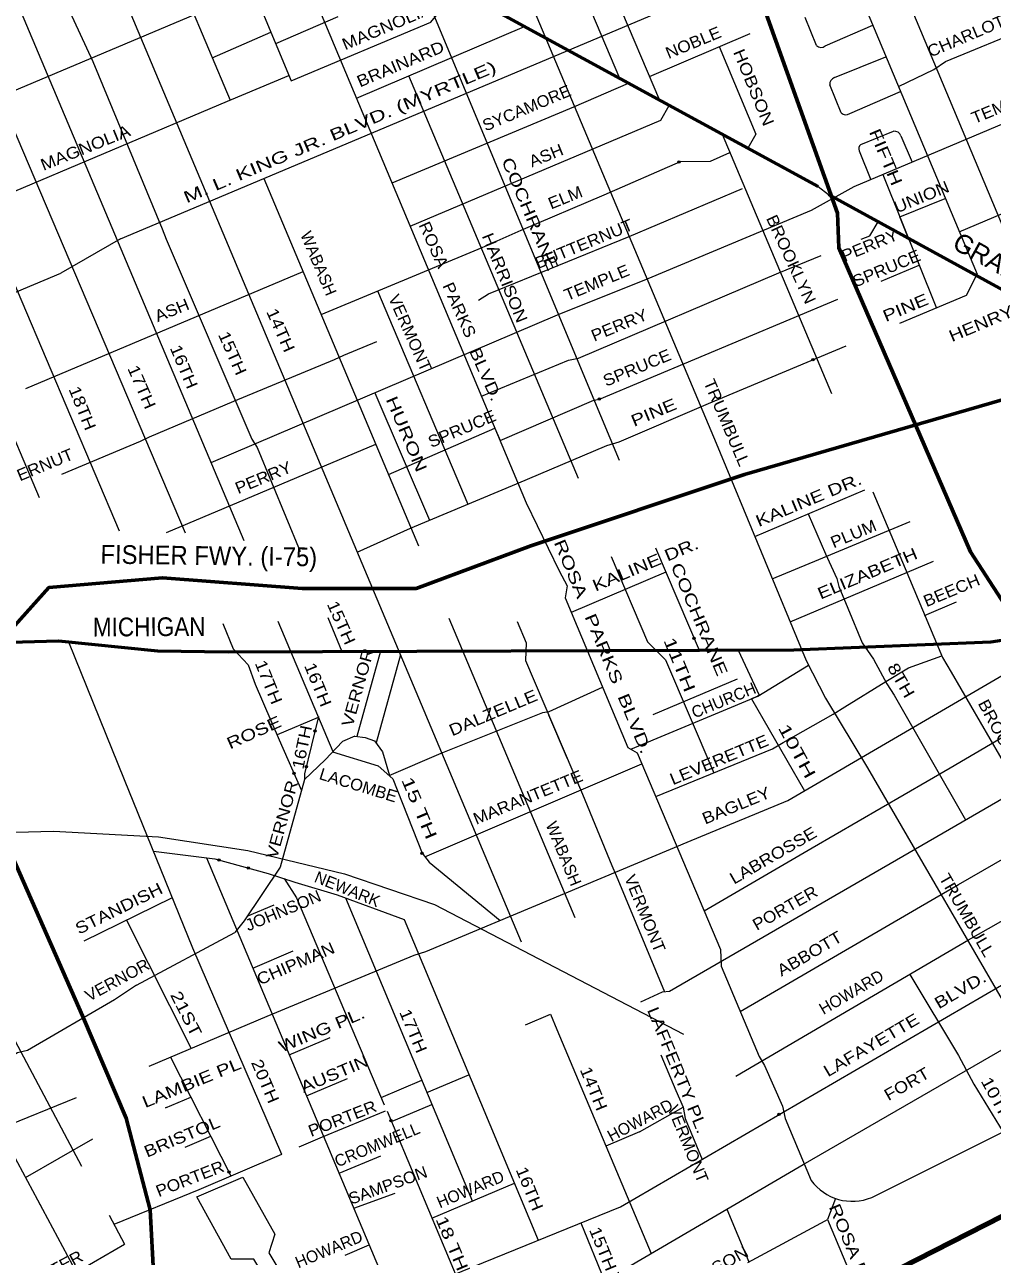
# Model space of a CAD drawing. Extents: x 34705 to 138605, y 34275 to 143551.
# Drawn here: x 89542 to 95747, y 96052 to 103945 of the extents above; entities that cross this region are included whole.
import ezdxf
from ezdxf.enums import TextEntityAlignment as Align

# ---------------------------------------------------------------- set-up
doc = ezdxf.new("R2010")
doc.units = 0
doc.header["$LTSCALE"] = 30
doc.header["$PDMODE"] = 32
doc.header["$PDSIZE"] = 15
doc.linetypes.add('MEDIUM_DASHED', pattern=[4.5, 3, -1.5])
for name, color, linetype, lineweight in [('1', 7, 'Continuous', 13), ('11', 7, 'Continuous', 13), ('50', 7, 'Continuous', 13), ('51', 7, 'Continuous', 35), ('58', 7, 'Continuous', 106), ('7', 7, 'MEDIUM_DASHED', 25)]:
    doc.layers.add(name, color=color, linetype=linetype, lineweight=lineweight)

msp = doc.modelspace()

# ---------------------------------------------------------------- linework, layer by layer
at = {"layer": '1'}
for p, q in [((88037.22, 107540.27), (90948.84, 100639.76)), ((92437.6, 106228.47), (93613.46, 103461.04)), ((94745.68, 104500.34), (95648.75, 102345.66)), ((91152.1, 103823.55), (91552.57, 103996.12)), ((94619.68, 103812.39), (94546.47, 103991.39)), ((90745.12, 103733), (91121.82, 103896.3)), ((91669.67, 103473.66), (92746.84, 103933.49)), ((93548.7, 103613.46), (94194.7, 103888.8)), ((94675.05, 103808.6), (94980.28, 103940.6)), ((93996.19, 103804.19), (94230.25, 103242.58)), ((94734.54, 103606), (95064.71, 103739.14)), ((90843.31, 103454.28), (91236.85, 103620)), ((94776.95, 103380.26), (94703.75, 103559.27)), ((89381.11, 103482.68), (90572.51, 100689.56)), ((94832.32, 103376.48), (95157.73, 103517.2)), ((88062.65, 102279.34), (90843.31, 103454.28)), ((89037.16, 103313.44), (90149.28, 100700.72)), ((94013.89, 103242.74), (94714.56, 101581.4)), ((94230.25, 103242.58), (94179.53, 103152.43)), ((94903.15, 103177.3), (95113.06, 103262.47)), ((95534.49, 102618.28), (96994.31, 103237.44)), ((95159.9, 103231.84), (95231.73, 103063.63)), ((94892.09, 103135.38), (94966.65, 102951.54)), ((91075.9, 102959.3), (92067.49, 100605.59)), ((95045.43, 102984.85), (95387.56, 102129.26)), ((94629.96, 102906.87), (94695.3, 102855.98)), ((90156.4, 102571.65), (89773.72, 102353.27)), ((95034.72, 102302.23), (95277.73, 102403.92)), ((89549.39, 101612.85), (91327.22, 102362.74)), ((91805, 102238.82), (92383.71, 100872.42)), ((89098.43, 102178.67), (89636.65, 100915.24)), ((91587.9, 101826.14), (91801.28, 101914.56)), ((91528.44, 101798.88), (91587.9, 101826.14)), ((90884.05, 101533.29), (91528.44, 101798.88)), ((91787.73, 101586.31), (92138.37, 100769.63)), ((89780.64, 101064.95), (90284.72, 101276.65)), ((90452.82, 100690.52), (91793.11, 101256.87)), ((91032.38, 101234.69), (91309.88, 100569.02)), ((94223.03, 100665.67), (94929.82, 100964.58)), ((93587.54, 100592.75), (93866.9, 99936.69)), ((94449.46, 100119.12), (95368.3, 100507.63)), ((93654.05, 100436.56), (93047, 100178.27)), ((95311.37, 100159.92), (95517.21, 100246.55)), ((91166.67, 100123.5), (91519.18, 99288.06)), ((91486.37, 100145.62), (91576.53, 99929.33)), ((92262.51, 100142.67), (93070.7, 98224.26)), ((93454.96, 96423.05), (99604.05, 99999.77)), ((91823.24, 99930.13), (91671.36, 99384.63)), ((91951.93, 99906.72), (91795.22, 99343.87)), ((94110.78, 99751.32), (93569.1, 99522.69)), ((91424.36, 99506.23), (91161.15, 99394.09)), ((91425.57, 99511.28), (91337.49, 99143.57)), ((92901.21, 99521.86), (93020.57, 99243.3)), ((91337.49, 99143.57), (91336.78, 99108.32)), ((92107.56, 98612.52), (93500.09, 99207.94)), ((90708, 98606.4), (92126.39, 95234.65)), ((93307.86, 98556.65), (93334.46, 98492.7)), ((93334.46, 98492.7), (93644.9, 97748.07)), ((89923.25, 98074.43), (90486.88, 98349.11)), ((91599.26, 98350.22), (92413.75, 96404.47)), ((88600.2, 98320.64), (90094.32, 95540.39)), ((90969.3, 98231.87), (91142.91, 98304.73)), ((90195.89, 98207.29), (90610.04, 97385.31)), ((91975.11, 98211.71), (92834.39, 96155.62)), ((90259.92, 97790.34), (90889.94, 98128.12)), ((89174.85, 98007.64), (89907.59, 96630.12)), ((91005.9, 97898.23), (91265.01, 98010.97)), ((92754, 97536.28), (92913.24, 97605.16)), ((91238.88, 97344.39), (91501.02, 97454.29)), ((90478.01, 97329.29), (90865.3, 96567.9)), ((94251.36, 97332.72), (94286.71, 97275.58)), ((94286.71, 97275.58), (94402.21, 97015.42)), ((91349.31, 97081.89), (91611.58, 97191.93)), ((91828.26, 97070.64), (92088.92, 97180.46)), ((92121.72, 97102.11), (92391.36, 97215.71)), ((91893.74, 96916.4), (92153.62, 97025.89)), ((93484.94, 96850.76), (93764.35, 97008.33)), ((94402.21, 97015.42), (94418.35, 96935.67)), ((91452.89, 96818.14), (91857.09, 96986.06)), ((91866.2, 96982.02), (92506.68, 95456.18)), ((94418.35, 96935.67), (94584.93, 96539.62)), ((93484.94, 96850.76), (93269.31, 96757.91)), ((89547.78, 96557.39), (89980.72, 96806.42)), ((90571.64, 96752.54), (90736.19, 96821.72)), ((91302.98, 96754.82), (91452.89, 96818.14)), ((91558.13, 96585.5), (91825.32, 96695.89)), ((91652.75, 96360.58), (91918.43, 96457.22)), ((92154.07, 96296.22), (92682.47, 96520.62)), ((93363.13, 96369.94), (93454.96, 96423.05)), ((94741.71, 96423.35), (94690.14, 96289.45)), ((90084.45, 96317.4), (90183.38, 96131.41)), ((94044.06, 96354.84), (94185.15, 96016.57)), ((94690.14, 96289.45), (94886.57, 95822.43)), ((93108.35, 96266.62), (93259.29, 95894.99)), ((91597.05, 96059.99), (91751.36, 96126.15))]:
    msp.add_line(p, q, dxfattribs=at)
at = {"layer": '1', "lineweight": 53}
for p, q in [((90110.84, 105370.56), (94629.96, 102906.87)), ((94695.3, 102855.98), (98364.86, 100847.24))]:
    msp.add_line(p, q, dxfattribs=at)
at = {"layer": '1'}
for points in [[(81747.75, 122290.24), (81921.27, 121957.09), (82052.47, 121930.85), (82118.06, 121884.91), (82590.36, 120959.69), (82629.72, 120926.88), (83141.38, 119927.85), (83541.52, 119133.87), (83541.52, 119022.31), (83495.61, 118937.01), (83436.57, 118877.95), (83449.69, 118733.59), (83456.25, 118661.41), (87277.28, 110821.66), (87605.27, 110172.03), (87736.46, 109929.24), (90285.3, 103864.22), (92725.99, 98068.68)], [(87924.47, 112104.52), (87935.44, 111856.64), (88221.88, 111308.88), (88769.61, 110355.76), (90167.23, 107043.23), (90212.11, 106947.03), (92757.3, 100881.83), (92968.86, 100445.74), (93020.15, 100349.54), (93007.33, 100272.59), (93410.61, 99313.84), (93470.43, 99278.08), (94003.29, 98018.06), (94007.57, 97912.37), (94251.36, 97332.72)], [(89620.31, 111530.82), (91301.99, 107601.17), (91366.1, 107415.19), (91673.83, 106703.33), (92808.58, 104033.88), (93975.39, 101263.41), (94552.01, 99871.59), (94676.64, 99628.81), (94945.59, 99182.6), (95948.05, 97457.03)], [(93695.7, 107547.6), (93857.2, 107315.71), (95985.91, 102236.51)], [(92273.44, 106158.02), (92495.54, 105632.89), (93356.65, 103601.04)], [(89318.01, 106151.54), (89120.57, 106072.53), (89061.53, 105947.86), (89061.53, 105862.55), (89709.3, 104295.91), (89979.33, 103708.16), (90424.31, 102635.76), (90450.55, 102570.15)], [(90045.33, 105405.98), (90304.59, 104779.85), (90859.58, 103460.99)], [(90576.58, 105116.66), (90647.47, 105035.61), (91251.37, 103585.13)], [(95144.29, 103549.28), (95370.73, 103656.57), (95446.38, 103708.96), (95987.58, 103930.16), (96605.73, 104193.38), (96625.21, 104146.06), (96936.12, 104314.36), (97524.26, 104662.79)], [(90156.4, 102571.65), (94024.26, 104202.29), (94870.72, 104551.4)], [(90738.5, 101138.28), (92958.63, 102086.3), (93540.56, 102319.15), (94588.03, 102755.74), (94861.54, 102907.09), (96744.08, 103703.14), (96837.19, 103772.99), (97713.93, 104285.09)], [(87827, 102821.34), (88640.53, 103170.17), (91008.18, 104169.25)], [(92137.1, 104071.39), (93174.01, 101584.06), (93353.56, 101153.61)], [(91251.37, 103585.13), (92146.6, 103961.27), (92198.44, 104022.64)], [(91899.52, 102930.38), (93063.38, 103419.35), (93413.35, 103570.13)], [(92003.56, 103618.4), (92764.49, 101813.89), (93091.94, 101038.9)], [(92013.86, 102653.46), (93622.03, 103332.04), (93674.28, 103427.88)], [(93747.05, 103068.19), (93938.65, 103070.68), (94063.57, 103124.95)], [(91442.75, 102088.53), (92475.63, 102517.07), (92725.86, 102627.67), (93258.25, 102855.05), (93747.05, 103068.19)], [(92452.35, 102179.44), (92452.35, 102179.44), (92516.36, 102220.19), (93418.35, 102586.93), (94145.77, 102895.45)], [(94905.78, 102569.96), (94960.47, 102592.75), (95015.25, 102680.83), (95209.52, 102574.49), (95153.93, 102713.52), (95445.05, 102831.67)], [(90450.55, 102570.15), (90999.7, 101288.86), (91032.38, 101234.69)], [(92471.07, 101563.91), (93028.46, 101795.25), (93092.47, 101806.89), (94378.54, 102354.08), (94649.7, 102465.05)], [(87161.55, 101274.03), (87939.48, 101579.86), (88306.1, 101737.03), (89773.72, 102353.27)], [(95154.26, 102031.87), (95581.68, 102211.46), (95648.75, 102345.66)], [(91874.75, 101063.07), (92557.1, 101358.91), (92590.23, 101279.95), (93192.43, 101539.65), (93227.43, 101545.94), (94755.83, 102185.52)], [(91674.88, 100564.59), (92015.9, 100718.33), (92696.76, 101003.57), (93274.99, 101247.95), (93354.76, 101270.88), (93927.53, 101516.4), (94810.38, 101887.37)], [(90284.72, 101276.65), (90342.86, 101304.06), (90884.05, 101533.29)], [(94980.43, 100951.02), (95187.4, 100460.27), (95427.18, 99889.61), (95483.49, 99796.13), (95916.43, 99048.07)], [(94565.73, 100810.6), (94676.64, 100554.03), (94748.8, 100396.54), (94761.92, 100344.05), (94820.96, 100206.25), (94912.79, 99983.15), (94984.95, 99878.16), (95070.22, 99720.67), (95116.14, 99648.49), (95573.72, 98849.07)], [(94335.77, 100393.54), (94634.18, 100517.44), (95220.13, 100760.84)], [(93303.85, 100537.36), (93535.25, 99989.71), (93650.47, 99873.89), (93961.12, 99151.55)], [(90812.65, 100107.58), (90879.88, 99944.8), (90975.33, 99843.7), (91021.24, 99719.03), (91174.64, 99362.74), (91317.4, 99038.36)], [(92700.97, 100119.46), (92757.93, 99984.79), (92753.93, 99869.87)], [(89822.75, 99990.51), (90181.6, 99108.77), (90619.46, 98029.36), (91188.7, 96706.54)], [(94116.67, 99937.49), (94252.63, 99648.61), (94243.24, 99642.87), (94202.04, 99625.67), (94542.7, 99036.08)], [(92753.93, 99869.87), (93118.14, 99014), (93307.86, 98556.65)], [(93428.89, 99302.91), (94243.24, 99642.87), (94567.63, 99841.17)], [(93588.48, 98998.92), (94336.35, 99305.24), (94406.18, 99345.99), (94726.24, 99526.44), (94801.89, 99573.01), (95063.76, 99736), (95209.24, 99823.32), (95422.36, 99900.85)], [(90341.13, 97271.2), (91097.91, 97592.35), (92040.63, 97982.37), (92114.36, 98006.08), (93683.61, 98661.67), (93789.34, 98705.66), (94435.28, 98973.43), (95918.22, 99838.32)], [(68439.64, 83130.91), (69240.62, 83379.94), (69351.18, 83443.98), (71166.8, 83996.99), (73724.39, 85148.13), (74227.76, 85392.62), (75135.57, 85904.88), (77195.6, 86958.51), (78743.53, 87721.08), (81322.94, 89059.96), (82067.81, 89449.98), (83313.14, 90160.16), (86113.68, 91749.34), (89963.15, 93974.49), (93143.39, 95827.08), (94534.21, 96642.05), (99929.58, 99752.11)], [(91880.28, 99133.8), (92212.31, 99276.13), (92864.07, 99538.08), (92904.8, 99543.91), (93248.17, 99700.03)], [(93898.5, 98265.83), (94592.4, 98670.73), (95476.93, 99182.99), (96092.18, 99543.48)], [(94102.64, 97206.72), (95593.32, 98079.88), (96600.06, 98650.35), (98206.88, 99594.86)], [(91660.2, 99386.35), (91579.35, 99350.97), (91468.17, 99234.7), (91336.78, 99108.32), (91181.39, 98547.2), (90950.19, 98203.45), (90889.94, 98128.12)], [(91660.2, 99386.35), (91725.9, 99376.24), (91786.54, 99356.02), (91837.08, 99285.25), (91881.56, 99132.68)], [(91516.89, 99285.66), (91808.8, 99196.37), (91903.88, 99113.14), (92090.1, 98635.8)], [(93492.55, 97684.04), (93632.22, 97748.07), (93677.3, 97751.12), (95511.85, 98813.35), (96265.19, 99248.27)], [(94130.13, 97620.96), (95378, 98347.65), (95529.31, 98434.97), (96436.14, 98956.57)], [(90368.05, 98649.12), (90761.13, 98599.72), (91103.14, 98505.9)], [(92090.1, 98635.8), (92136.66, 98577.59), (92591.86, 98205.57)], [(91103.14, 98505.9), (91274.65, 98451.22), (91546.85, 98369.54), (91975.11, 98211.71)], [(91207.21, 98472.72), (91286.45, 98350.34), (91848.51, 97022.81)], [(90259.92, 97790.34), (90118.26, 97696.67), (89560.52, 97372.09), (89497, 97356.72), (89242.4, 97205.72), (89176.52, 97200.37)], [(95216.66, 97857.76), (95529.41, 97338.72), (95627.8, 97154.99), (95815.09, 96848.98)], [(92913.24, 97605.16), (92954.72, 97506.05), (93558.44, 96070.29)], [(93620.98, 97343.08), (93717.83, 97114.7), (93764.01, 97009.1), (93777.15, 96936.87), (93886.16, 96673.86)], [(94973.04, 96430.02), (95820.27, 96851.61), (96531.68, 97212.52), (96828.47, 97381.34)], [(87348.77, 95890.22), (87903.33, 96185.57), (87941.55, 96113.13), (88633.43, 96486.33), (88988.41, 96672.61), (89378.3, 96870.53), (89874.49, 97069.92)], [(90451.05, 97006.43), (90446.15, 97004.41), (90608.34, 97073.06)], [(90116.07, 96257.96), (90661.46, 96480.51), (91191.02, 96707.53)], [(91747.97, 95706.14), (91889.33, 95767.41), (92279.23, 95930.4), (93363.13, 96369.94)], [(94179.23, 96013.36), (94673.87, 96281.14), (94690.23, 96289.28)], [(88815.04, 95358.99), (89488.25, 95726.62), (89850.55, 95937.47), (90183.38, 96131.41)]]:
    msp.add_lwpolyline(points, dxfattribs=at)
at = {"layer": '1', "lineweight": 53}
msp.add_lwpolyline([(70273.25, 98655.39), (71057.35, 98936.8), (71901.7, 99280.47), (72734.73, 99461.12), (73549.47, 99618.3), (74194.43, 99751.98), (74462.66, 99868.63), (74760.14, 99892.09), (75412.24, 99851.32), (76511.78, 99857.14), (78835.21, 99868.78), (80080.52, 99857.14), (86770.24, 99915.34), (86956.45, 99956.09), (88909.68, 99973.56), (89759.8, 99996.86), (90394.28, 99932.82), (90847.72, 99926.99), (94474.35, 99938.64), (95736.38, 99991), (96334.87, 100081.57)], dxfattribs=at)
at = {"layer": '1'}
for centre, radius, start, end in [((94649.33, 103839.35), 40.08, 222.27388, 309.90416), ((94749.23, 103562.8), 45.63, 108.79235, 184.44263), ((94806.61, 103407.23), 40.08, 222.27388, 309.90416), ((95116.76, 103216.99), 45.63, 18.99808, 94.64837), ((94930.22, 103147.74), 40.08, 132.47962, 197.95901), ((94848.59, 96731.32), 325.99, 216.0192, 292.44115)]:
    msp.add_arc(centre, radius, start, end, dxfattribs=at)
for p in [(93738.42, 103064.26), (94404.36, 103029.86), (94595.87, 101797.56), (93227.43, 101545.94), (93834.52, 100012.74), (91403.67, 99419.83), (91269.4, 99147.43), (91348.63, 99190.09), (90789.33, 98591.98), (92090.1, 98635.8), (90975.79, 98540.83), (91891.37, 96922.04), (94379.58, 96962.18), (90852.84, 96592.4)]:
    msp.add_point(p, dxfattribs=at)
at = {"layer": '50'}
msp.add_line((92169.12, 98306.86), (93766.07, 97476.34), dxfattribs=at)
msp.add_lwpolyline([(72952.8, 95508.64), (78064.89, 96622.26), (81430.09, 97291.04), (86167.76, 98196.23), (89160.46, 98763.08), (89727.54, 98776.38), (90401.7, 98740.87), (90973.35, 98653.39), (91592.71, 98503.02), (92169.12, 98306.86)], dxfattribs=at)
at = {"layer": '51', "lineweight": 60}
for points in [[(89237.66, 115479.85), (91499.64, 110952.67), (93420.76, 106565.37), (94042.42, 104827.01), (94275.43, 104074.61), (94754.53, 102737.63), (94761.52, 102513.8), (95607.58, 100567.59), (95901.26, 100112.95), (96166.96, 99847.16), (96705.36, 99210.66), (97075.95, 98895.9), (97236.78, 98686.07), (97390.6, 98581.15), (97562.53, 98387.67)], [(100708.3, 104431.99), (100301.7, 104046.37), (99460.75, 103701.33), (98388.89, 103068.27), (97510.88, 102543.58), (96878.03, 102018.88), (96266.56, 101672.41), (94157.06, 101062.17), (92788.73, 100605.91), (92053.25, 100332.16), (91322.06, 100332.16), (90426.94, 100400.6), (89697.17, 100337.86), (89332.28, 99932.93), (89286.67, 99488.08), (89309.48, 99071.74), (89383.59, 98792.29), (89913.82, 97593.19), (90193.19, 96937.32), (90347.13, 96349.89), (90369.93, 95910.74)]]:
    msp.add_lwpolyline(points, dxfattribs=at)
at = {"layer": '58'}
msp.add_lwpolyline([(109288.57, 102020.28), (107945.92, 101285.08), (107188.24, 100823.21), (106858.2, 100701.93), (106111.49, 100351.64), (105606.31, 100041.45), (105294.49, 99854.44), (104132.31, 99432.6), (103251.52, 99077.41), (102563.33, 98804.04), (102396.46, 98745.29), (102193.7, 98668.47), (101874.28, 98521.51), (101323.51, 98272.16), (101245.34, 98201.3), (98594.35, 97249.65), (98526.88, 97383.5), (96460.77, 96641.8), (94939.86, 95864.74)], dxfattribs=at)
at = {"layer": '7', "linetype": 'Continuous', "lineweight": 13}
msp.add_lwpolyline([(90940.86, 96561), (91145.86, 96195.59), (91107.24, 96075.3), (93932.18, 91369.35), (93844.25, 91320.13), (91012.91, 96033.52), (90866.14, 96033.62), (90647.37, 96433.23)], close=True, dxfattribs=at)

# ---------------------------------------------------------------- texts
at = {"layer": '11'}
for s, height, rotation, width, p in [('MAGNOLIA', 75, 22.958, 1.15, (91877.38, 103898.61)), ('CHARLOTTE', 75, 23.07, 1.1, (95657.15, 103864.92)), ('NOBLE', 75, 22.546, 1.1, (93843.4, 103795.66)), ('BRAINARD', 75, 23.009, 1.15, (91966.52, 103658.55)), ('HOBSON ', 75, 292.339, 1.2, (94188.68, 103513.19)), ('M. L. KING JR. BLVD. (MYRTLE)', 75, 22.999, 1.45, (91577.56, 103222.36)), ('SYCAMORE', 75, 22.759, 1.05, (92775.53, 103376.44)), ('TEMPLE', 75, 22.446, 1.1, (95835.53, 103392.11)), ('MAGNOLIA', 75, 22, 1.15, (89945.45, 103121.63)), ('FIFTH', 75, 292.86, 1.35, (95028.99, 103081.87)), ('ASH', 75, 22.057, 1.1, (92899.45, 103071.77)), ('COCHRANE    ', 75, 292.855, 1.35, (92777.85, 102648.13)), ('UNION', 75, 22.409, 1.15, (95306.39, 102806.47)), ('ELM', 75, 22.091, 1.1, (93022.57, 102802.73)), ('ROSA', 75, 294.001, 1.1, (92131, 102519.11)), ('BUTTERNUT', 75, 22.445, 1.1, (93142.23, 102505.79)), ('BROOKLYN', 75, 294.634, 1.1, (94422.3, 102425.86)), ('HARRISON', 75, 291.999, 1.15, (92586.54, 102309.07)), ('PERRY', 75, 22.409, 1.1, (94975.09, 102497.03)), ('SPRUCE', 75, 22.509, 1.1, (95082.12, 102349.03)), ('TEMPLE', 75, 22.446, 1.1, (93224.33, 102257.89)), ('PARKS', 75, 294.002, 1.1, (92295.69, 102102.01)), ('VERMONT', 75, 293.996, 1.05, (91979.25, 101954.32)), ('PINE', 75, 22.622, 1.3, (95203.96, 102097.09)), ('ASH', 75, 22.057, 1.1, (90500.73, 102080.69)), ('HENRY ', 75, 22.805, 1.25, (95705.75, 102002.04)), ('14TH', 75, 293.999, 1.2, (91149.79, 101971.84)), ('PERRY', 75, 22.409, 1.1, (93369.51, 101985.35)), ('15TH', 75, 293.998, 1.2, (90840.8, 101824.61)), ('16TH', 75, 292.998, 1.2, (90529.39, 101738.72)), ('BLVD.', 75, 294, 1.25, (92464.25, 101689.96)), ('SPRUCE', 75, 22.509, 1.1, (93482.44, 101711.85)), ('17TH', 75, 293.629, 1.2, (90258.8, 101608.12)), ('TRUMBULL', 75, 293.003, 1.1, (94009.67, 101380.86)), ('18TH', 75, 292.004, 1.2, (89878.08, 101473.38)), ('HURON   ', 75, 292.856, 1.4, (91979.42, 101253.43)), ('PINE', 75, 22.622, 1.3, (93589.67, 101425.65)), ('SPRUCE', 75, 22.853, 1.1, (92360.69, 101321.27)), ('BUTTERNUT', 75, 22.445, 1.1, (89554.4, 101035.49)), ('PERRY', 75, 22.409, 1.1, (91086.96, 101008.4)), ('KALINE DR.', 75, 22.673, 1.3, (94583, 100864.73)), ('PLUM', 75, 22.697, 1.1, (94870.38, 100647.59)), ('ROSA   PARKS  BLVD. ', 75, 292.459, 1.4, (93223.17, 99928.3)), ('KALINE DR.', 75, 22.673, 1.3, (93536.56, 100451.17)), ('FISHER FWY. (I-75)', 120, 359.262, 0.95, (90722.68, 100482.58)), ('ELIZABETH', 75, 22.931, 1.25, (94960.16, 100393.63)), ('COCHRANE    ', 75, 292.855, 1.35, (93863.07, 100050.77)), ('BEECH', 75, 22.716, 1.1, (95499.52, 100285.15)), ('15TH', 75, 293.998, 1.2, (91538.76, 100097.57)), ('MICHIGAN', 120, 0.34, 0.9, (90341.25, 100026.4)), ('11TH       ', 75, 292.289, 1.5, (93761.98, 99694.69)), ('VERNOR ', 75, 74.458, 1.2, (91718.31, 99704.12)), ('17TH', 75, 292.161, 1.2, (91072.25, 99717.87)), ('16TH', 75, 292.161, 1.2, (91388.36, 99701.96)), ('8TH', 75, 299.944, 1.25, (95129.17, 99724.35)), ('DALZELLE', 75, 22.856, 1.2, (92560.27, 99501.04)), ('BROOKLYN', 75, 298.087, 1.1, (95796.18, 99325.33)), ('ROSE ', 75, 24.06, 1.3, (91044.28, 99383.11)), ('16TH', 75, 78.458, 1.15, (91357.44, 99307.96)), ('10TH   ', 75, 298.621, 1.55, (94492.57, 99215.46)), ('LEVERETTE', 75, 22.58, 1.15, (94008.84, 99200.22)), ('LACOMBE', 75, 342.845, 1.05, (91671.05, 99036)), ('MARANTETTE', 75, 22.396, 1.1, (92783.26, 98959.89)), ('VERNOR ', 75, 74.458, 1.2, (91232.59, 98858.27)), ('15 TH ', 75, 292.856, 1.55, (92046.5, 98891.34)), ('BAGLEY', 75, 22.516, 1.15, (94118.61, 98907.26)), ('LABROSSE', 75, 30.016, 1.15, (94359.53, 98589.3)), ('VERMONT', 75, 292.238, 1.05, (93484.85, 98236.14)), ('TRUMBULL', 75, 299.917, 1.1, (95550.31, 98220.59)), ('STANDISH', 75, 26.34, 1.2, (90163.2, 98247.99)), ('PORTER', 75, 29.879, 1.1, (94435.9, 98252.35)), ('JOHNSON', 75, 22.768, 1.05, (91213.55, 98234.11)), ('ABBOTT', 75, 30.353, 1.15, (94593.41, 97960.71)), ('CHIPMAN', 75, 23.517, 1.15, (91294.95, 97894.54)), ('VERNOR', 75, 28.504, 1.05, (90153.47, 97790.44)), ('BLVD.', 75, 30.519, 1.25, (95559.47, 97726.85)), ('21ST', 75, 297.047, 1.3, (90544.23, 97590.23)), ('17TH', 75, 292.829, 1.2, (91999.75, 97482.51)), ('LAFFERTY PL.', 75, 292.233, 1.25, (93695.09, 97231.51)), ('WING PL.', 75, 22.748, 1.3, (91461.76, 97470.47)), ('LAFAYETTE', 75, 30.516, 1.2, (94989.45, 97374.7)), ('AUSTIN', 75, 22.761, 1.25, (91543.1, 97187.21)), ('LAMBIE PL', 75, 22.346, 1.3, (90626.7, 97130.05)), ('20TH', 75, 293.072, 1.2, (91050.38, 97160.1)), ('14TH', 75, 292.235, 1.2, (93156.16, 97113.33)), ('FORT', 75, 29.938, 1.15, (95216.46, 97125.02)), ('10TH', 75, 298.622, 1.25, (95744.03, 97041.56)), ('PORTER', 75, 21.448, 1.1, (91593.04, 96901.02)), ('VERMONT', 75, 292.233, 1.05, (93760.47, 96759.48)), ('BRISTOL', 75, 22.803, 1.2, (90565.2, 96784.37)), ('PORTER', 75, 21.448, 1.1, (90615.74, 96515.38)), ('SAMPSON', 75, 19.989, 1.05, (91884.39, 96473.12)), ('16TH', 75, 292.233, 1.2, (92745.25, 96472.24)), ('ROSA PARKS BLVD. ', 75, 292.459, 1.3, (94944.39, 95770.88)), ('18 TH', 75, 292.909, 1.35, (92247.65, 96120.8)), ('15TH', 75, 292.234, 1.2, (93215.51, 96086.58)), ('PORTER', 75, 27.904, 1.1, (89721.43, 95920.85)), ('WEST JEFFERSON', 75, 28.846, 1.15, (93730.67, 95803.82))]:
    msp.add_text(s, height=height, rotation=rotation, dxfattribs=dict(at, width=width)).set_placement(p, align=Align.CENTER)
for s, height, rotation, p in [('WABASH', 75, 292.789, (91392.12, 102400.45)), ('GRAND RIVER', 120, 330.982, (95969.2, 102244.85)), ('CHURCH', 75, 22.396, (94037.99, 99581.34)), ('WABASH', 75, 292.238, (92963.67, 98618.94)), ('NEWARK', 75, 338.032, (91597.51, 98371.44)), ('HOWARD', 75, 30.191, (94861.24, 97713.23)), ('HOWARD', 75, 28.032, (93505.64, 96891.72)), ('CROMWELL', 75, 22.452, (91816.56, 96733.13)), ('HOWARD', 75, 22.835, (92414.84, 96448.26)), ('HOWARD', 75, 22.835, (91507.75, 96063.19))]:
    msp.add_text(s, height=height, rotation=rotation, dxfattribs=at).set_placement(p, align=Align.CENTER)

doc.saveas('drawing.dxf')
